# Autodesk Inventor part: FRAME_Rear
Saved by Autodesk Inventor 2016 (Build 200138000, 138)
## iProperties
Created: 2016-03
Part Number: FRAME_Rear
Material: Generic
Document SubType Name: Modeling
Designer: bongo_000
Density: 1 g/cm^3
Appearance: Default
Author: bongo_000
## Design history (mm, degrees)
feature "SOLID1"
body "Solid1"
